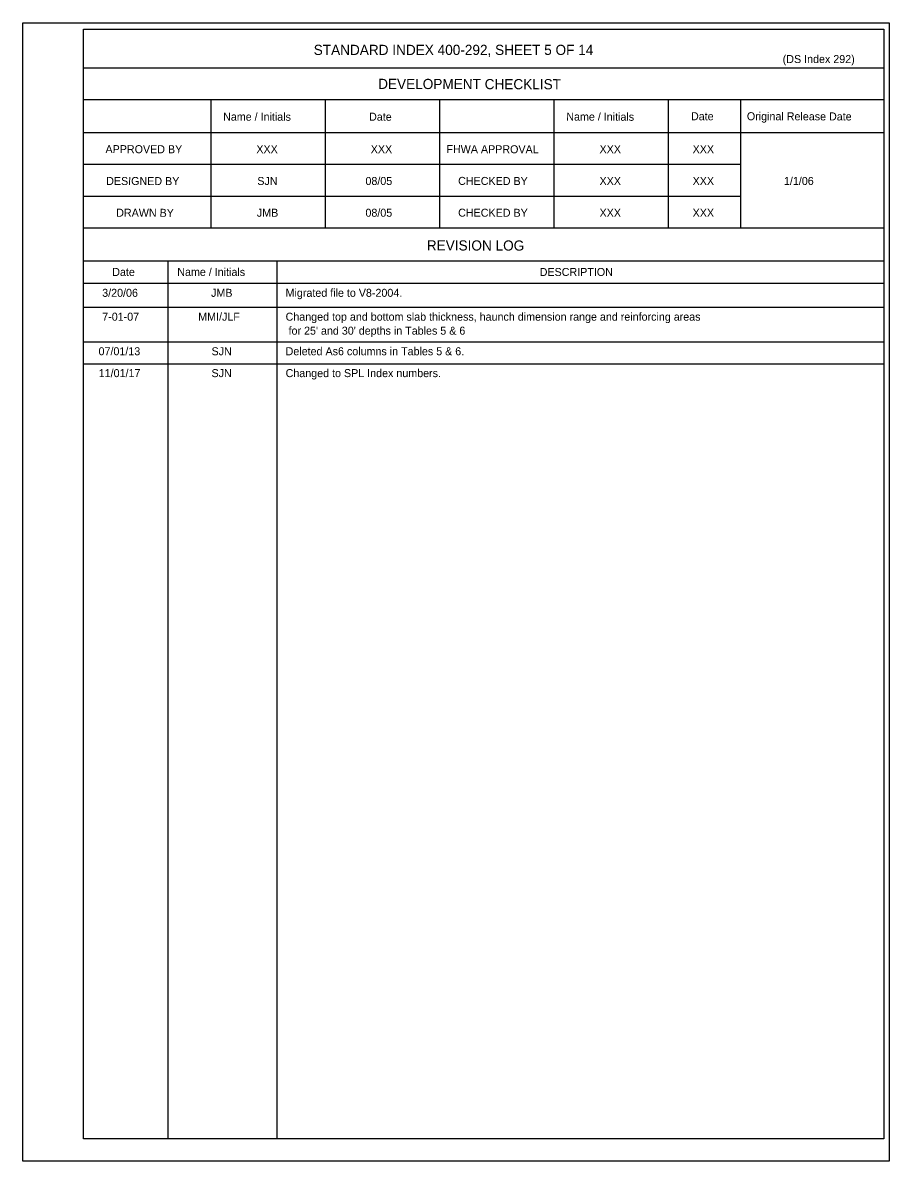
# Model space of a CAD drawing. Extents: x 10346.98 to 10349.19, y 76399.48 to 76400.59.
# Drawn here: x 10348.508 to 10349.19, y 76399.632 to 76400.528 of the extents above; entities that cross this region are included whole.
import ezdxf

# ---------------------------------------------------------------- set-up
doc = ezdxf.new("R2010")
doc.units = 0
for name, color, linetype in [('AdhocPoint_dp', 7, 'Continuous'), ('Border', 7, 'Continuous'), ('PlotBorder_dp', 7, 'Continuous')]:
    doc.layers.add(name, color=color, linetype=linetype)

msp = doc.modelspace()

# ---------------------------------------------------------------- linework, layer by layer
at = {"layer": 'Border'}
for p, q in [((10349.18582, 76400.49202), (10348.55623, 76400.49202)), ((10349.18582, 76400.46702), (10348.55623, 76400.46702)), ((10348.65623, 76400.46702), (10348.65623, 76400.36615)), ((10348.74623, 76400.46702), (10348.74623, 76400.36615)), ((10348.83623, 76400.46702), (10348.83623, 76400.36615)), ((10348.92623, 76400.46702), (10348.92623, 76400.36615)), ((10349.01623, 76400.46702), (10349.01623, 76400.36615)), ((10349.07295, 76400.46702), (10349.07295, 76400.36615)), ((10349.18582, 76400.44115), (10348.55623, 76400.44115)), ((10349.07295, 76400.41615), (10348.55623, 76400.41615)), ((10349.07295, 76400.39115), (10348.55623, 76400.39115)), ((10349.18582, 76400.36615), (10348.55623, 76400.36615)), ((10349.18582, 76400.34028), (10348.55623, 76400.34028)), ((10348.62249, 76400.34028), (10348.62249, 76399.64945)), ((10348.70819, 76400.34028), (10348.70819, 76399.64945)), ((10349.18582, 76400.32266), (10348.55623, 76400.32266)), ((10348.5084, 76399.63191), (10348.5084, 76399.63191))]:
    msp.add_line(p, q, dxfattribs=at)
for points in [[(10348.5084, 76400.52774), (10349.19007, 76400.52774), (10349.19007, 76399.63191), (10348.5084, 76399.63191)], [(10348.55624, 76400.52266), (10349.18582, 76400.52266), (10349.18582, 76399.64945), (10348.55624, 76399.64945)]]:
    msp.add_lwpolyline(points, close=True, dxfattribs=at)
at = {"layer": 'PlotBorder_dp'}
for p, q in [((10348.55624, 76400.30386), (10349.18582, 76400.30386)), ((10348.55625, 76400.27668), (10349.18583, 76400.27668)), ((10348.55625, 76400.25947), (10349.18583, 76400.25947))]:
    msp.add_line(p, q, dxfattribs=at)

# ---------------------------------------------------------------- texts
at = {"layer": 'AdhocPoint_dp'}
for s, height, p in [('STANDARD INDEX 400-292, SHEET 5 OF 14', 0.008, (10348.7373, 76400.50241)), ('(DS Index 292)', 0.0063, (10349.10627, 76400.49605)), ('XXX', 0.0063, (10348.69217, 76400.42511)), ('XXX', 0.0063, (10348.78217, 76400.42511)), ('XXX', 0.0063, (10348.96217, 76400.42511)), ('XXX', 0.0063, (10349.0354, 76400.42511)), ('SJN', 0.0063, (10348.69293, 76400.40011)), ('08/05', 0.0063, (10348.77799, 76400.40011)), ('XXX', 0.0063, (10348.96217, 76400.40011)), ('XXX', 0.0063, (10349.0354, 76400.40011)), ('1/1/06', 0.0063, (10349.10725, 76400.40011)), ('JMB', 0.0063, (10348.69258, 76400.37511)), ('08/05', 0.0063, (10348.77799, 76400.37511)), ('XXX', 0.0063, (10348.96217, 76400.37511)), ('XXX', 0.0063, (10349.0354, 76400.37511)), ('DESCRIPTION', 0.0063, (10348.91509, 76400.3285)), ('3/20/06', 0.0063, (10348.5709, 76400.3121)), ('JMB', 0.0063, (10348.65654, 76400.3121)), ('Migrated file to V8-2004.', 0.0063, (10348.71517, 76400.3121)), ('7-01-07', 0.0063, (10348.57092, 76400.2933)), ('MMI/JLF', 0.0063, (10348.64641, 76400.2933)), ('Changed top and bottom slab thickness, haunch dimension range and reinforcing areas ', 0.0063, (10348.71518, 76400.2933)), (" for 25' and 30' depths in Tables 5 & 6", 0.0063, (10348.71518, 76400.28231)), ('07/01/13', 0.0063, (10348.56802, 76400.26611)), ('SJN', 0.0063, (10348.65691, 76400.26611)), ('Deleted As6 columns in Tables 5 & 6.', 0.0063, (10348.71519, 76400.26611)), ('11/01/17', 0.0063, (10348.56816, 76400.24891)), ('SJN', 0.0063, (10348.65691, 76400.24891)), ('Changed to SPL Index numbers.', 0.0063, (10348.71519, 76400.24891))]:
    msp.add_text(s, height=height, dxfattribs=at).set_placement(p)
for s, height, p in [('DEVELOPMENT CHECKLIST', 0.008, (10348.78798, 76400.47567)), ('Name / Initials', 0.0063, (10348.666, 76400.45074)), ('Date', 0.0063, (10348.78083, 76400.45069)), ('Name / Initials', 0.0063, (10348.936, 76400.45074)), ('Date', 0.0063, (10349.03411, 76400.45105)), ('Original Release Date', 0.0063, (10349.07807, 76400.45105)), ('APPROVED BY', 0.0063, (10348.57347, 76400.42517)), ('FHWA APPROVAL', 0.0063, (10348.8417, 76400.42517)), ('DESIGNED BY', 0.0063, (10348.574, 76400.40012)), ('CHECKED BY', 0.0063, (10348.85092, 76400.40017)), ('DRAWN BY', 0.0063, (10348.5819, 76400.37512)), ('CHECKED BY', 0.0063, (10348.85092, 76400.37517)), ('REVISION LOG', 0.008, (10348.82626, 76400.34861)), ('Date', 0.0063, (10348.5788, 76400.32852)), ('Name / Initials', 0.0063, (10348.62995, 76400.32857))]:
    msp.add_text(s, height=height, rotation=359.87563, dxfattribs=at).set_placement(p)

doc.saveas('drawing.dxf')
